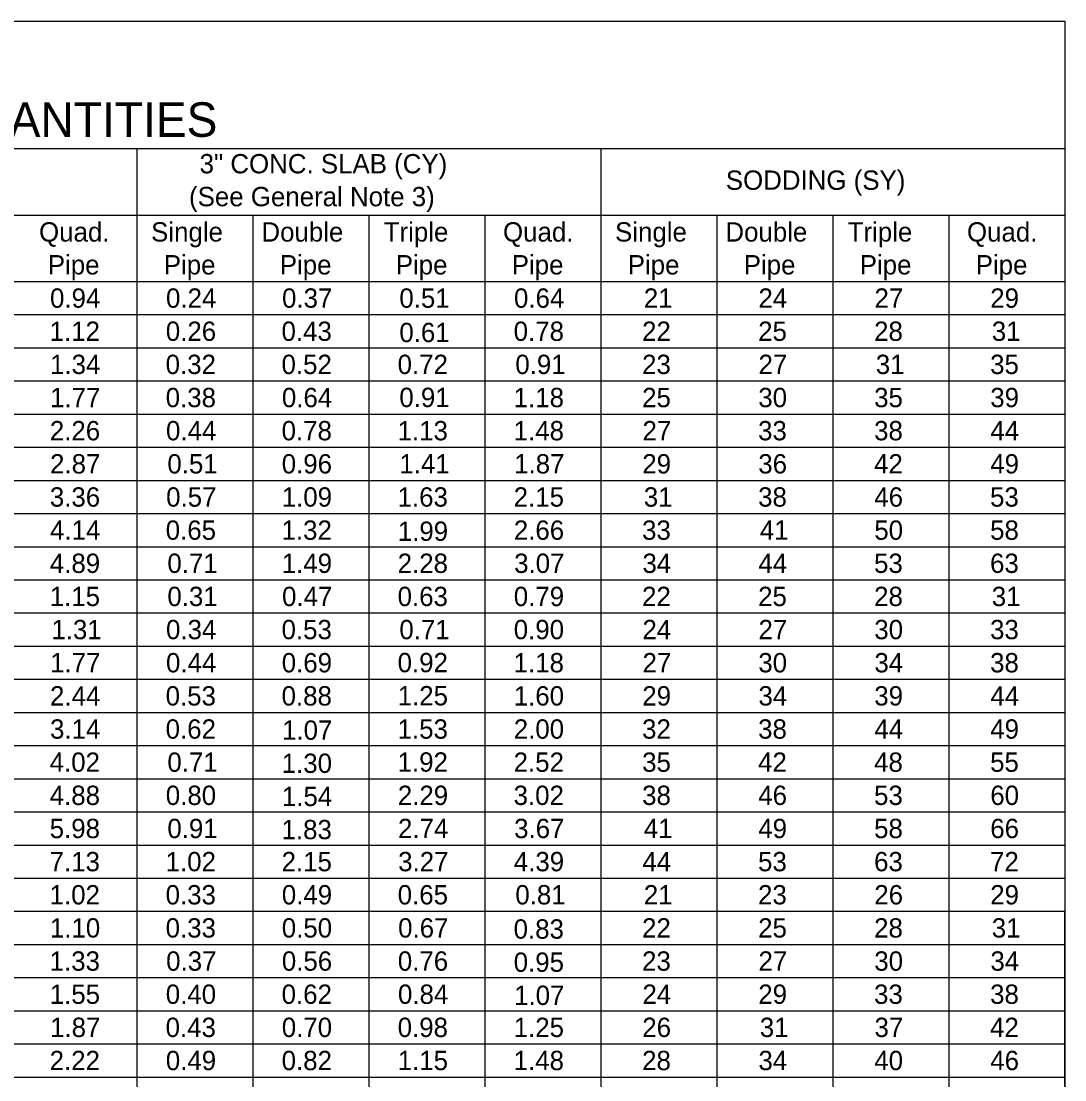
# Model space of a CAD drawing. Extents: x -1.3 to 14.4, y 0 to 7.8.
# Drawn here: x 9.681 to 13.46, y 3.92 to 7.752 of the extents above; entities that cross this region are included whole.
import ezdxf

# ---------------------------------------------------------------- set-up
doc = ezdxf.new("R2010")
doc.units = 0
doc.layers.add('Table', color=7, linetype='Continuous')

msp = doc.modelspace()

# ---------------------------------------------------------------- linework, layer by layer
at = {"layer": 'Table'}
msp.add_line((1.94, 7.7524), (13.46, 7.7524), dxfattribs=at)
for points in [[(13.46, 7.7524), (13.46, 7.17), (13.46, 6.81), (13.46, 6.69), (13.46, 6.57), (13.46, 6.45), (13.46, 6.33), (13.46, 6.21), (13.46, 6.09), (13.46, 5.97), (13.46, 5.85), (13.46, 5.73), (13.46, 5.61), (13.46, 5.49), (13.46, 5.37), (13.46, 5.25), (13.46, 5.13), (13.46, 5.01), (13.46, 4.89), (13.46, 4.77), (13.46, 4.65), (13.46, 4.53), (13.46, 4.41), (13.46, 4.29), (13.46, 4.17), (13.46, 4.05), (13.46, 3.93), (13.46, 3.81)], [(13.46, 7.29), (11.78, 7.29), (10.1, 7.29), (8.42, 7.29), (8.06, 7.29), (6.38, 7.29), (6.02, 7.29), (5.66, 7.29), (5.3, 7.29), (4.94, 7.29), (4.52, 7.29), (4.04, 7.29), (3.62, 7.29), (3.2, 7.29), (2.9, 7.29), (2.6, 7.29), (2.3, 7.29), (1.94, 7.29)], [(10.1, 7.29), (10.1, 6.81), (10.1, 6.69), (10.1, 6.57), (10.1, 6.45), (10.1, 6.33), (10.1, 6.21), (10.1, 6.09), (10.1, 5.97), (10.1, 5.85), (10.1, 5.73), (10.1, 5.61), (10.1, 5.49), (10.1, 5.37), (10.1, 5.25), (10.1, 5.13), (10.1, 5.01), (10.1, 4.89), (10.1, 4.77), (10.1, 4.65), (10.1, 4.53), (10.1, 4.41), (10.1, 4.29), (10.1, 4.17), (10.1, 4.05), (10.1, 3.93), (10.1, 3.81)], [(11.78, 7.29), (11.78, 6.81), (11.78, 6.69), (11.78, 6.57), (11.78, 6.45), (11.78, 6.33), (11.78, 6.21), (11.78, 6.09), (11.78, 5.97), (11.78, 5.85), (11.78, 5.73), (11.78, 5.61), (11.78, 5.49), (11.78, 5.37), (11.78, 5.25), (11.78, 5.13), (11.78, 5.01), (11.78, 4.89), (11.78, 4.77), (11.78, 4.65), (11.78, 4.53), (11.78, 4.41), (11.78, 4.29), (11.78, 4.17), (11.78, 4.05), (11.78, 3.93), (11.78, 3.81)], [(8.42, 7.05), (8.84, 7.05), (9.26, 7.05), (9.68, 7.05), (10.1, 7.05), (10.52, 7.05), (10.94, 7.05), (11.36, 7.05), (11.78, 7.05), (12.2, 7.05), (12.62, 7.05), (13.04, 7.05), (13.46, 7.05)], [(10.52, 7.05), (10.52, 6.81), (10.52, 6.69), (10.52, 6.57), (10.52, 6.45), (10.52, 6.33), (10.52, 6.21), (10.52, 6.09), (10.52, 5.97), (10.52, 5.85), (10.52, 5.73), (10.52, 5.61), (10.52, 5.49), (10.52, 5.37), (10.52, 5.25), (10.52, 5.13), (10.52, 5.01), (10.52, 4.89), (10.52, 4.77), (10.52, 4.65), (10.52, 4.53), (10.52, 4.41), (10.52, 4.29), (10.52, 4.17), (10.52, 4.05), (10.52, 3.93), (10.52, 3.81)], [(10.94, 7.05), (10.94, 6.81), (10.94, 6.69), (10.94, 6.57), (10.94, 6.45), (10.94, 6.33), (10.94, 6.21), (10.94, 6.09), (10.94, 5.97), (10.94, 5.85), (10.94, 5.73), (10.94, 5.61), (10.94, 5.49), (10.94, 5.37), (10.94, 5.25), (10.94, 5.13), (10.94, 5.01), (10.94, 4.89), (10.94, 4.77), (10.94, 4.65), (10.94, 4.53), (10.94, 4.41), (10.94, 4.29), (10.94, 4.17), (10.94, 4.05), (10.94, 3.93), (10.94, 3.81)], [(11.36, 7.05), (11.36, 6.81), (11.36, 6.69), (11.36, 6.57), (11.36, 6.45), (11.36, 6.33), (11.36, 6.21), (11.36, 6.09), (11.36, 5.97), (11.36, 5.85), (11.36, 5.73), (11.36, 5.61), (11.36, 5.49), (11.36, 5.37), (11.36, 5.25), (11.36, 5.13), (11.36, 5.01), (11.36, 4.89), (11.36, 4.77), (11.36, 4.65), (11.36, 4.53), (11.36, 4.41), (11.36, 4.29), (11.36, 4.17), (11.36, 4.05), (11.36, 3.93), (11.36, 3.81)], [(12.2, 7.05), (12.2, 6.81), (12.2, 6.69), (12.2, 6.57), (12.2, 6.45), (12.2, 6.33), (12.2, 6.21), (12.2, 6.09), (12.2, 5.97), (12.2, 5.85), (12.2, 5.73), (12.2, 5.61), (12.2, 5.49), (12.2, 5.37), (12.2, 5.25), (12.2, 5.13), (12.2, 5.01), (12.2, 4.89), (12.2, 4.77), (12.2, 4.65), (12.2, 4.53), (12.2, 4.41), (12.2, 4.29), (12.2, 4.17), (12.2, 4.05), (12.2, 3.93), (12.2, 3.81)], [(12.62, 7.05), (12.62, 6.81), (12.62, 6.69), (12.62, 6.57), (12.62, 6.45), (12.62, 6.33), (12.62, 6.21), (12.62, 6.09), (12.62, 5.97), (12.62, 5.85), (12.62, 5.73), (12.62, 5.61), (12.62, 5.49), (12.62, 5.37), (12.62, 5.25), (12.62, 5.13), (12.62, 5.01), (12.62, 4.89), (12.62, 4.77), (12.62, 4.65), (12.62, 4.53), (12.62, 4.41), (12.62, 4.29), (12.62, 4.17), (12.62, 4.05), (12.62, 3.93), (12.62, 3.81)], [(13.04, 7.05), (13.04, 6.81), (13.04, 6.69), (13.04, 6.57), (13.04, 6.45), (13.04, 6.33), (13.04, 6.21), (13.04, 6.09), (13.04, 5.97), (13.04, 5.85), (13.04, 5.73), (13.04, 5.61), (13.04, 5.49), (13.04, 5.37), (13.04, 5.25), (13.04, 5.13), (13.04, 5.01), (13.04, 4.89), (13.04, 4.77), (13.04, 4.65), (13.04, 4.53), (13.04, 4.41), (13.04, 4.29), (13.04, 4.17), (13.04, 4.05), (13.04, 3.93), (13.04, 3.81)], [(6.38, 6.81), (6.8, 6.81), (7.22, 6.81), (7.64, 6.81), (8.06, 6.81), (8.42, 6.81), (8.84, 6.81), (9.26, 6.81), (9.68, 6.81), (10.1, 6.81), (10.52, 6.81), (10.94, 6.81), (11.36, 6.81), (11.78, 6.81), (12.2, 6.81), (12.62, 6.81), (13.04, 6.81), (13.46, 6.81)], [(6.38, 6.69), (6.8, 6.69), (7.22, 6.69), (7.64, 6.69), (8.06, 6.69), (8.42, 6.69), (8.84, 6.69), (9.26, 6.69), (9.68, 6.69), (10.1, 6.69), (10.52, 6.69), (10.94, 6.69), (11.36, 6.69), (11.78, 6.69), (12.2, 6.69), (12.62, 6.69), (13.04, 6.69), (13.46, 6.69)], [(6.38, 6.57), (6.8, 6.57), (7.22, 6.57), (7.64, 6.57), (8.06, 6.57), (8.42, 6.57), (8.84, 6.57), (9.26, 6.57), (9.68, 6.57), (10.1, 6.57), (10.52, 6.57), (10.94, 6.57), (11.36, 6.57), (11.78, 6.57), (12.2, 6.57), (12.62, 6.57), (13.04, 6.57), (13.46, 6.57)], [(6.38, 6.45), (6.8, 6.45), (7.22, 6.45), (7.64, 6.45), (8.06, 6.45), (8.42, 6.45), (8.84, 6.45), (9.26, 6.45), (9.68, 6.45), (10.1, 6.45), (10.52, 6.45), (10.94, 6.45), (11.36, 6.45), (11.78, 6.45), (12.2, 6.45), (12.62, 6.45), (13.04, 6.45), (13.46, 6.45)], [(6.38, 6.33), (6.8, 6.33), (7.22, 6.33), (7.64, 6.33), (8.06, 6.33), (8.42, 6.33), (8.84, 6.33), (9.26, 6.33), (9.68, 6.33), (10.1, 6.33), (10.52, 6.33), (10.94, 6.33), (11.36, 6.33), (11.78, 6.33), (12.2, 6.33), (12.62, 6.33), (13.04, 6.33), (13.46, 6.33)], [(6.38, 6.21), (6.8, 6.21), (7.22, 6.21), (7.64, 6.21), (8.06, 6.21), (8.42, 6.21), (8.84, 6.21), (9.26, 6.21), (9.68, 6.21), (10.1, 6.21), (10.52, 6.21), (10.94, 6.21), (11.36, 6.21), (11.78, 6.21), (12.2, 6.21), (12.62, 6.21), (13.04, 6.21), (13.46, 6.21)], [(6.38, 6.09), (6.8, 6.09), (7.22, 6.09), (7.64, 6.09), (8.06, 6.09), (8.42, 6.09), (8.84, 6.09), (9.26, 6.09), (9.68, 6.09), (10.1, 6.09), (10.52, 6.09), (10.94, 6.09), (11.36, 6.09), (11.78, 6.09), (12.2, 6.09), (12.62, 6.09), (13.04, 6.09), (13.46, 6.09)], [(6.38, 5.97), (6.8, 5.97), (7.22, 5.97), (7.64, 5.97), (8.06, 5.97), (8.42, 5.97), (8.84, 5.97), (9.26, 5.97), (9.68, 5.97), (10.1, 5.97), (10.52, 5.97), (10.94, 5.97), (11.36, 5.97), (11.78, 5.97), (12.2, 5.97), (12.62, 5.97), (13.04, 5.97), (13.46, 5.97)], [(6.38, 5.85), (6.8, 5.85), (7.22, 5.85), (7.64, 5.85), (8.06, 5.85), (8.42, 5.85), (8.84, 5.85), (9.26, 5.85), (9.68, 5.85), (10.1, 5.85), (10.52, 5.85), (10.94, 5.85), (11.36, 5.85), (11.78, 5.85), (12.2, 5.85), (12.62, 5.85), (13.04, 5.85), (13.46, 5.85)], [(6.38, 5.73), (6.8, 5.73), (7.22, 5.73), (7.64, 5.73), (8.06, 5.73), (8.42, 5.73), (8.84, 5.73), (9.26, 5.73), (9.68, 5.73), (10.1, 5.73), (10.52, 5.73), (10.94, 5.73), (11.36, 5.73), (11.78, 5.73), (12.2, 5.73), (12.62, 5.73), (13.04, 5.73), (13.46, 5.73)], [(6.38, 5.61), (6.8, 5.61), (7.22, 5.61), (7.64, 5.61), (8.06, 5.61), (8.42, 5.61), (8.84, 5.61), (9.26, 5.61), (9.68, 5.61), (10.1, 5.61), (10.52, 5.61), (10.94, 5.61), (11.36, 5.61), (11.78, 5.61), (12.2, 5.61), (12.62, 5.61), (13.04, 5.61), (13.46, 5.61)], [(6.38, 5.49), (6.8, 5.49), (7.22, 5.49), (7.64, 5.49), (8.06, 5.49), (8.42, 5.49), (8.84, 5.49), (9.26, 5.49), (9.68, 5.49), (10.1, 5.49), (10.52, 5.49), (10.94, 5.49), (11.36, 5.49), (11.78, 5.49), (12.2, 5.49), (12.62, 5.49), (13.04, 5.49), (13.46, 5.49)], [(6.38, 5.37), (6.8, 5.37), (7.22, 5.37), (7.64, 5.37), (8.06, 5.37), (8.42, 5.37), (8.84, 5.37), (9.26, 5.37), (9.68, 5.37), (10.1, 5.37), (10.52, 5.37), (10.94, 5.37), (11.36, 5.37), (11.78, 5.37), (12.2, 5.37), (12.62, 5.37), (13.04, 5.37), (13.46, 5.37)], [(6.38, 5.25), (6.8, 5.25), (7.22, 5.25), (7.64, 5.25), (8.06, 5.25), (8.42, 5.25), (8.84, 5.25), (9.26, 5.25), (9.68, 5.25), (10.1, 5.25), (10.52, 5.25), (10.94, 5.25), (11.36, 5.25), (11.78, 5.25), (12.2, 5.25), (12.62, 5.25), (13.04, 5.25), (13.46, 5.25)], [(6.38, 5.13), (6.8, 5.13), (7.22, 5.13), (7.64, 5.13), (8.06, 5.13), (8.42, 5.13), (8.84, 5.13), (9.26, 5.13), (9.68, 5.13), (10.1, 5.13), (10.52, 5.13), (10.94, 5.13), (11.36, 5.13), (11.78, 5.13), (12.2, 5.13), (12.62, 5.13), (13.04, 5.13), (13.46, 5.13)], [(6.38, 5.01), (6.8, 5.01), (7.22, 5.01), (7.64, 5.01), (8.06, 5.01), (8.42, 5.01), (8.84, 5.01), (9.26, 5.01), (9.68, 5.01), (10.1, 5.01), (10.52, 5.01), (10.94, 5.01), (11.36, 5.01), (11.78, 5.01), (12.2, 5.01), (12.62, 5.01), (13.04, 5.01), (13.46, 5.01)], [(6.38, 4.89), (6.8, 4.89), (7.22, 4.89), (7.64, 4.89), (8.06, 4.89), (8.42, 4.89), (8.84, 4.89), (9.26, 4.89), (9.68, 4.89), (10.1, 4.89), (10.52, 4.89), (10.94, 4.89), (11.36, 4.89), (11.78, 4.89), (12.2, 4.89), (12.62, 4.89), (13.04, 4.89), (13.46, 4.89)], [(6.38, 4.77), (6.8, 4.77), (7.22, 4.77), (7.64, 4.77), (8.06, 4.77), (8.42, 4.77), (8.84, 4.77), (9.26, 4.77), (9.68, 4.77), (10.1, 4.77), (10.52, 4.77), (10.94, 4.77), (11.36, 4.77), (11.78, 4.77), (12.2, 4.77), (12.62, 4.77), (13.04, 4.77), (13.46, 4.77)], [(6.38, 4.65), (6.8, 4.65), (7.22, 4.65), (7.64, 4.65), (8.06, 4.65), (8.42, 4.65), (8.84, 4.65), (9.26, 4.65), (9.68, 4.65), (10.1, 4.65), (10.52, 4.65), (10.94, 4.65), (11.36, 4.65), (11.78, 4.65), (12.2, 4.65), (12.62, 4.65), (13.04, 4.65), (13.46, 4.65)], [(6.38, 4.53), (6.8, 4.53), (7.22, 4.53), (7.64, 4.53), (8.06, 4.53), (8.42, 4.53), (8.84, 4.53), (9.26, 4.53), (9.68, 4.53), (10.1, 4.53), (10.52, 4.53), (10.94, 4.53), (11.36, 4.53), (11.78, 4.53), (12.2, 4.53), (12.62, 4.53), (13.04, 4.53), (13.46, 4.53)], [(13.46, 3.69), (13.46, 4.53), (13.46, 4.41), (13.46, 4.29), (13.46, 4.17), (13.46, 4.05), (13.46, 3.93), (13.46, 3.81)], [(6.38, 4.41), (6.8, 4.41), (7.22, 4.41), (7.64, 4.41), (8.06, 4.41), (8.42, 4.41), (8.84, 4.41), (9.26, 4.41), (9.68, 4.41), (10.1, 4.41), (10.52, 4.41), (10.94, 4.41), (11.36, 4.41), (11.78, 4.41), (12.2, 4.41), (12.62, 4.41), (13.04, 4.41), (13.46, 4.41)], [(6.38, 4.29), (6.8, 4.29), (7.22, 4.29), (7.64, 4.29), (8.06, 4.29), (8.42, 4.29), (8.84, 4.29), (9.26, 4.29), (9.68, 4.29), (10.1, 4.29), (10.52, 4.29), (10.94, 4.29), (11.36, 4.29), (11.78, 4.29), (12.2, 4.29), (12.62, 4.29), (13.04, 4.29), (13.46, 4.29)], [(6.38, 4.17), (6.8, 4.17), (7.22, 4.17), (7.64, 4.17), (8.06, 4.17), (8.42, 4.17), (8.84, 4.17), (9.26, 4.17), (9.68, 4.17), (10.1, 4.17), (10.52, 4.17), (10.94, 4.17), (11.36, 4.17), (11.78, 4.17), (12.2, 4.17), (12.62, 4.17), (13.04, 4.17), (13.46, 4.17)], [(6.38, 4.05), (6.8, 4.05), (7.22, 4.05), (7.64, 4.05), (8.06, 4.05), (8.42, 4.05), (8.84, 4.05), (9.26, 4.05), (9.68, 4.05), (10.1, 4.05), (10.52, 4.05), (10.94, 4.05), (11.36, 4.05), (11.78, 4.05), (12.2, 4.05), (12.62, 4.05), (13.04, 4.05), (13.46, 4.05)], [(6.38, 3.93), (6.8, 3.93), (7.22, 3.93), (7.64, 3.93), (8.06, 3.93), (8.42, 3.93), (8.84, 3.93), (9.26, 3.93), (9.68, 3.93), (10.1, 3.93), (10.52, 3.93), (10.94, 3.93), (11.36, 3.93), (11.78, 3.93), (12.2, 3.93), (12.62, 3.93), (13.04, 3.93), (13.46, 3.93)]]:
    msp.add_lwpolyline(points, dxfattribs=at)

# ---------------------------------------------------------------- texts
for s, height, p in [('SINGLE AND MULTIPLE CORRUGATED METAL PIPE DIMENSIONS AND QUANTITIES', 0.125, (3.6948, 7.3337)), ('3" CONC. SLAB (CY)', 0.07, (10.3271, 7.2014)), ('SODDING (SY)', 0.07, (12.2325, 7.1419)), ('(See General Note 3)', 0.07, (10.2888, 7.0824)), ('Quad.', 0.07, (9.7457, 6.9545)), ('Single', 0.07, (10.1514, 6.9545)), ('Double', 0.07, (10.5509, 6.9545)), ('Triple', 0.07, (10.9937, 6.9545)), ('Quad.', 0.07, (11.4257, 6.9545)), ('Single', 0.07, (11.8314, 6.9545)), ('Double', 0.07, (12.2309, 6.9545)), ('Triple', 0.07, (12.6737, 6.9545)), ('Quad.', 0.07, (13.1057, 6.9545)), ('Pipe', 0.07, (9.7773, 6.8355)), ('Pipe', 0.07, (10.1973, 6.8355)), ('Pipe', 0.07, (10.6173, 6.8355)), ('Pipe', 0.07, (11.0373, 6.8355)), ('Pipe', 0.07, (11.4573, 6.8355)), ('Pipe', 0.07, (11.8773, 6.8355)), ('Pipe', 0.07, (12.2973, 6.8355)), ('Pipe', 0.07, (12.7173, 6.8355)), ('Pipe', 0.07, (13.1373, 6.8355)), ('0.24', 0.07, (10.2054, 6.715)), ('0.37', 0.07, (10.6256, 6.715)), ('0.51', 0.07, (11.0503, 6.715)), ('0.64', 0.07, (11.4654, 6.715)), ('0.26', 0.07, (10.2047, 6.595)), ('0.43', 0.07, (10.6236, 6.595)), ('0.61', 0.07, (11.0503, 6.5905)), ('0.78', 0.07, (11.4642, 6.595)), ('0.32', 0.07, (10.204, 6.475)), ('0.52', 0.07, (10.6237, 6.475)), ('0.72', 0.07, (11.044, 6.475)), ('0.91', 0.07, (11.4703, 6.475)), ('0.38', 0.07, (10.2042, 6.355)), ('0.64', 0.07, (10.625, 6.355)), ('0.91', 0.07, (11.0503, 6.3555)), ('1.18', 0.07, (11.4642, 6.355)), ('0.44', 0.07, (10.2054, 6.235)), ('0.78', 0.07, (10.6239, 6.235)), ('1.13', 0.07, (11.0439, 6.235)), ('1.48', 0.07, (11.4642, 6.235)), ('0.51', 0.07, (10.2103, 6.115)), ('0.96', 0.07, (10.6244, 6.115)), ('1.41', 0.07, (11.0503, 6.115)), ('1.87', 0.07, (11.466, 6.115)), ('0.57', 0.07, (10.2059, 5.995)), ('1.09', 0.07, (10.6244, 5.995)), ('1.63', 0.07, (11.0439, 5.995)), ('2.15', 0.07, (11.4643, 5.995)), ('0.65', 0.07, (10.2043, 5.875)), ('1.32', 0.07, (10.6237, 5.875)), ('1.99', 0.07, (11.0447, 5.871)), ('2.66', 0.07, (11.4648, 5.875)), ('0.71', 0.07, (10.2103, 5.755)), ('1.49', 0.07, (10.6244, 5.755)), ('2.28', 0.07, (11.0442, 5.755)), ('3.07', 0.07, (11.466, 5.755)), ('0.31', 0.07, (10.2103, 5.635)), ('0.47', 0.07, (10.6256, 5.635)), ('0.63', 0.07, (11.044, 5.635)), ('0.79', 0.07, (11.4647, 5.635)), ('0.34', 0.07, (10.2054, 5.515)), ('0.53', 0.07, (10.6237, 5.515)), ('0.71', 0.07, (11.0503, 5.515)), ('0.90', 0.07, (11.4645, 5.515)), ('0.44', 0.07, (10.2054, 5.395)), ('0.69', 0.07, (10.6244, 5.395)), ('0.92', 0.07, (11.044, 5.3955)), ('1.18', 0.07, (11.4642, 5.395)), ('0.53', 0.07, (10.204, 5.275)), ('0.88', 0.07, (10.6239, 5.275)), ('1.25', 0.07, (11.0443, 5.2755)), ('1.60', 0.07, (11.4645, 5.275)), ('0.62', 0.07, (10.204, 5.155)), ('1.07', 0.07, (10.6256, 5.151)), ('1.53', 0.07, (11.044, 5.155)), ('2.00', 0.07, (11.4646, 5.155)), ('0.71', 0.07, (10.2103, 5.035)), ('1.30', 0.07, (10.6243, 5.031)), ('1.92', 0.07, (11.044, 5.0355)), ('2.52', 0.07, (11.4641, 5.035)), ('0.80', 0.07, (10.2046, 4.915)), ('2.29', 0.07, (11.0448, 4.915)), ('3.02', 0.07, (11.464, 4.915)), ('1.54', 0.07, (10.6251, 4.911)), ('0.91', 0.07, (10.2103, 4.795)), ('1.83', 0.07, (10.6237, 4.791)), ('2.74', 0.07, (11.0454, 4.795)), ('3.67', 0.07, (11.4659, 4.795)), ('1.02', 0.07, (10.204, 4.675)), ('2.15', 0.07, (10.624, 4.675)), ('3.27', 0.07, (11.046, 4.675)), ('4.39', 0.07, (11.4648, 4.675)), ('1.02', 0.07, (9.784, 4.555)), ('0.33', 0.07, (10.204, 4.555)), ('0.49', 0.07, (10.6247, 4.555)), ('0.65', 0.07, (11.0443, 4.555)), ('0.81', 0.07, (11.4703, 4.555)), ('0.33', 0.07, (10.204, 4.435)), ('0.50', 0.07, (10.6246, 4.435)), ('0.67', 0.07, (11.0459, 4.435)), ('0.83', 0.07, (11.464, 4.431)), ('1.33', 0.07, (9.784, 4.315)), ('0.37', 0.07, (10.2059, 4.315)), ('0.56', 0.07, (10.6248, 4.315)), ('0.76', 0.07, (11.0448, 4.315)), ('0.95', 0.07, (11.4643, 4.311)), ('1.55', 0.07, (9.7843, 4.195)), ('0.40', 0.07, (10.2045, 4.195)), ('0.62', 0.07, (10.624, 4.195)), ('0.84', 0.07, (11.0454, 4.195)), ('1.07', 0.07, (11.4659, 4.191)), ('1.87', 0.07, (9.7856, 4.075)), ('0.43', 0.07, (10.2039, 4.075)), ('0.70', 0.07, (10.6246, 4.075)), ('0.98', 0.07, (11.0442, 4.075)), ('1.25', 0.07, (11.4643, 4.075)), ('0.49', 0.07, (10.2047, 3.955)), ('0.82', 0.07, (10.6241, 3.955)), ('1.15', 0.07, (11.0443, 3.955)), ('1.48', 0.07, (11.4642, 3.955))]:
    msp.add_text(s, height=height, dxfattribs=at).set_placement(p)
for s, p in [('0.94', (9.7854, 6.715)), ('21', (11.9355, 6.715)), ('24', (12.3506, 6.715)), ('27', (12.7708, 6.715)), ('29', (13.19, 6.715)), ('1.12', (9.784, 6.595)), ('22', (11.9292, 6.595)), ('25', (12.3495, 6.595)), ('28', (12.7694, 6.595)), ('31', (13.1955, 6.595)), ('1.34', (9.7854, 6.475)), ('23', (11.9292, 6.475)), ('27', (12.3508, 6.475)), ('31', (12.7755, 6.475)), ('35', (13.1895, 6.475)), ('1.77', (9.7856, 6.355)), ('25', (11.9295, 6.355)), ('30', (12.3501, 6.355)), ('35', (12.7695, 6.355)), ('39', (13.19, 6.355)), ('2.26', (9.7847, 6.235)), ('27', (11.9308, 6.235)), ('33', (12.3492, 6.235)), ('38', (12.7694, 6.235)), ('44', (13.1906, 6.235)), ('2.87', (9.7856, 6.115)), ('29', (11.93, 6.115)), ('36', (12.35, 6.115)), ('42', (12.7692, 6.115)), ('49', (13.19, 6.115)), ('3.36', (9.7847, 5.995)), ('31', (11.9355, 5.995)), ('38', (12.3494, 5.995)), ('46', (12.77, 5.995)), ('53', (13.1892, 5.995)), ('4.14', (9.7854, 5.875)), ('33', (11.9292, 5.875)), ('41', (12.3555, 5.875)), ('50', (12.7701, 5.875)), ('58', (13.1894, 5.875)), ('4.89', (9.7847, 5.755)), ('34', (11.9306, 5.755)), ('53', (12.7692, 5.755)), ('63', (13.1892, 5.755)), ('44', (12.3506, 5.755)), ('1.15', (9.7843, 5.635)), ('22', (11.9292, 5.635)), ('25', (12.3495, 5.635)), ('28', (12.7694, 5.635)), ('31', (13.1955, 5.635)), ('1.31', (9.7903, 5.515)), ('24', (11.9306, 5.515)), ('27', (12.3508, 5.515)), ('30', (12.7701, 5.515)), ('33', (13.1892, 5.515)), ('1.77', (9.7856, 5.395)), ('27', (11.9308, 5.395)), ('30', (12.3501, 5.395)), ('34', (12.7706, 5.395)), ('38', (13.1894, 5.395)), ('2.44', (9.7854, 5.275)), ('29', (11.93, 5.275)), ('34', (12.3506, 5.275)), ('39', (12.77, 5.275)), ('44', (13.1906, 5.275)), ('3.14', (9.7854, 5.155)), ('32', (11.9292, 5.155)), ('38', (12.3494, 5.155)), ('44', (12.7706, 5.155)), ('49', (13.19, 5.155)), ('4.02', (9.784, 5.035)), ('35', (11.9295, 5.035)), ('42', (12.3492, 5.035)), ('48', (12.7694, 5.035)), ('55', (13.1895, 5.035)), ('4.88', (9.7842, 4.915)), ('38', (11.9294, 4.915)), ('46', (12.35, 4.915)), ('53', (12.7692, 4.915)), ('60', (13.1901, 4.915)), ('5.98', (9.7842, 4.795)), ('41', (11.9355, 4.795)), ('49', (12.35, 4.795)), ('58', (12.7694, 4.795)), ('66', (13.19, 4.795)), ('7.13', (9.784, 4.675)), ('44', (11.9306, 4.675)), ('53', (12.3492, 4.675)), ('63', (12.7692, 4.675)), ('72', (13.1892, 4.675)), ('21', (11.9355, 4.555)), ('23', (12.3492, 4.555)), ('26', (12.77, 4.555)), ('29', (13.19, 4.555)), ('1.10', (9.7849, 4.435)), ('22', (11.9292, 4.435)), ('25', (12.3495, 4.435)), ('28', (12.7694, 4.435)), ('31', (13.1955, 4.435)), ('23', (11.9292, 4.315)), ('27', (12.3508, 4.315)), ('30', (12.7701, 4.315)), ('34', (13.1906, 4.315)), ('24', (11.9306, 4.195)), ('29', (12.35, 4.195)), ('33', (12.7692, 4.195)), ('38', (13.1894, 4.195)), ('26', (11.93, 4.075)), ('31', (12.3555, 4.075)), ('37', (12.7708, 4.075)), ('42', (13.1892, 4.075)), ('2.22', (9.784, 3.955)), ('28', (11.9294, 3.955)), ('34', (12.3506, 3.955)), ('40', (12.7701, 3.955)), ('46', (13.19, 3.955))]:
    msp.add_text(s, height=0.07, rotation=0, dxfattribs=at).set_placement(p)

doc.saveas('drawing.dxf')
